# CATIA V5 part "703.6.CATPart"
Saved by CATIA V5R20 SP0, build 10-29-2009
Part number: 703.6
Revision: QUALSIASI
Definition: SCONOSCIUTO
Nomenclature: 703.6
Source: Unknown
Bounding box of the stored display mesh (mm): x -60 to 60, y -60 to 60, z 0 to 30
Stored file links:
  C:\Users\Utente\Desktop\IO LAVORO\3D X SITO CF\X 3D SITO CF 27-09-2020\703\703.6.CATPart
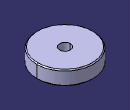
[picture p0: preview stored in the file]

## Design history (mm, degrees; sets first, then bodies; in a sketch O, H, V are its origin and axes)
Body1 "NONE" (main body)
  Solid1: solid without history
